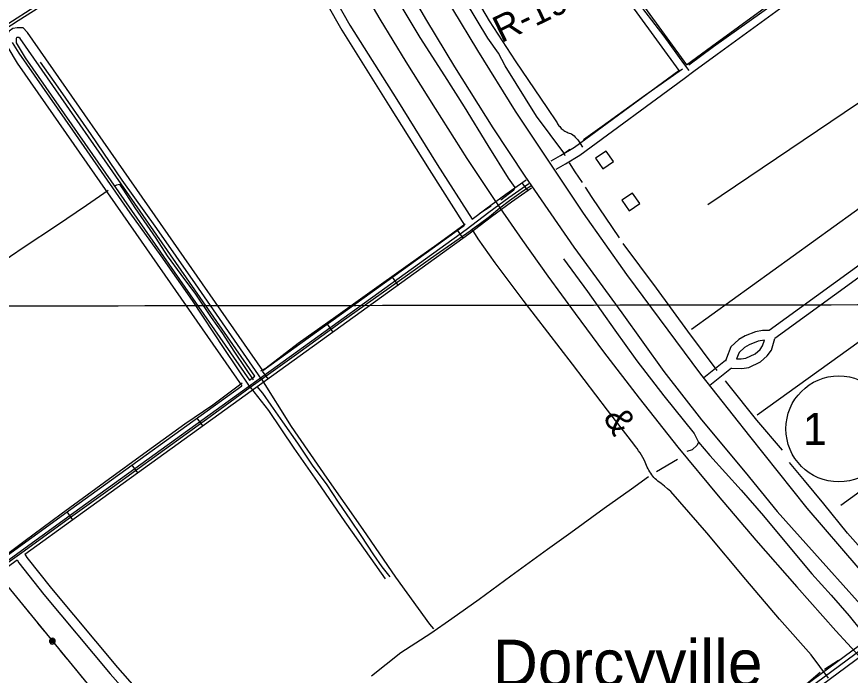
# Model space of a CAD drawing. Extents: x 3324125 to 3362000, y 600753 to 626151.
# Drawn here: x 3330131 to 3332729, y 611048 to 613099 of the extents above; entities that cross this region are included whole.
import ezdxf

# ---------------------------------------------------------------- set-up
doc = ezdxf.new("R2010")
doc.units = 0
for name, color, linetype in [('V-BLDG-OTLN', 7, 'Continuous'), ('V-DTCH-CNTR', 7, 'Continuous'), ('V-GRID-MAJR', 7, 'Continuous'), ('V-RAIL-IDEN', 7, 'Continuous'), ('V-RAIL-TRAK', 7, 'Continuous'), ('V-RIVR-RANG-IDEN', 7, 'Continuous'), ('V-ROAD-CNTR', 7, 'Continuous'), ('V-ROAD-IDEN', 7, 'Continuous'), ('V-TOPO-GNAM-IDEN', 7, 'Continuous'), ('V-TOPO-SHOR', 7, 'Continuous'), ('V-UTIL-LINE', 7, 'Continuous')]:
    doc.layers.add(name, color=color, linetype=linetype)

msp = doc.modelspace()

# ---------------------------------------------------------------- linework, layer by layer
at = {"layer": 'V-BLDG-OTLN'}
for points in [[(3331934.7, 612657.8), (3331957.1, 612624.7), (3331990.3, 612647.2), (3331967.8, 612680.3)], [(3332016.7, 612527.2), (3332039.1, 612494.1), (3332072.2, 612516.5), (3332049.8, 612549.6)]]:
    msp.add_lwpolyline(points, close=True, dxfattribs=at)
at = {"layer": 'V-DTCH-CNTR'}
msp.add_line((3331881, 612711.8), (3331893.9, 612692.5), dxfattribs=at)
for points in [[(3331510.5, 613243.8), (3331602.7, 613085.8), (3331684, 612961.1), (3331784.8, 612812.3), (3331813.1, 612771.5), (3331814.7, 612768.2), (3331816.4, 612765.1), (3331818.4, 612762), (3331820.5, 612759), (3331822.8, 612756.2), (3331825.2, 612753.5), (3331827.8, 612750.9), (3331830.5, 612748.5), (3331833.4, 612746.2), (3331836.3, 612744.1), (3331839.4, 612742.1), (3331842.6, 612740.3), (3331845.9, 612738.7), (3331849.2, 612737.3), (3331852.7, 612736.1), (3331856.1, 612735), (3331859.7, 612734.2), (3331863.7, 612730.9), (3331867.6, 612727.5), (3331871.2, 612723.8), (3331874.7, 612720), (3331878, 612716), (3331881, 612711.8)], [(3329755.3, 612855.6), (3330029.3, 613029.3), (3330259.4, 613178.2), (3330303.3, 613212.2), (3330298.1, 613227.7)], [(3332226.6, 612930.8), (3332209.3, 612953.2), (3332148.2, 613038.2), (3332054.3, 613161.7)], [(3330858.5, 611945), (3330777, 612065.4), (3330678.8, 612214.6), (3330581.2, 612354), (3330484.7, 612488.2), (3330404.4, 612603.5), (3330305.7, 612745.2), (3330209.8, 612882.3), (3330138.7, 612985.4), (3330117.3, 613018.2)], [(3330893.1, 611969.7), (3330809.9, 612091.3), (3330687.4, 612267), (3330567.3, 612439.2), (3330459.8, 612589.6), (3330362.8, 612731.9), (3330259.4, 612879.3), (3330204.5, 612956.5)], [(3329611.6, 611047.1), (3329753.3, 611148.2), (3329885.2, 611244.6), (3329999.3, 611324.9), (3330146.2, 611430), (3330290.8, 611535.2), (3330429, 611633.4), (3330572.5, 611737.9), (3330733.2, 611854), (3330858.5, 611945), (3330893.1, 611969.7), (3331002.8, 612048.1), (3331141.6, 612148), (3331291.4, 612254.3), (3331437.7, 612357.7), (3331544.3, 612432.3), (3331550.6, 612436.9), (3331571.9, 612452.5), (3331603.6, 612476.7), (3331636.6, 612503.3), (3331666, 612525.8), (3331710.4, 612557), (3331736.1, 612574)], [(3332660.5, 611038.6), (3332607, 611111.3), (3332508.2, 611222.7), (3332403, 611346.3), (3332281.5, 611491.7), (3332168.9, 611620.1), (3332159, 611628.5), (3332149, 611636.7), (3332138.8, 611644.6), (3332128.4, 611652.4), (3332124.4, 611656.1), (3332120.5, 611660), (3332116.7, 611664), (3332113.2, 611668.2), (3332109.8, 611672.5), (3332106.6, 611677), (3332103.5, 611681.6), (3332100.7, 611686.3), (3332098.1, 611691.1), (3332095.6, 611696), (3332093.4, 611701.1), (3332091.4, 611706.2), (3332089.5, 611711.4), (3332085.7, 611718.7), (3332081.7, 611726), (3332077.6, 611733.1), (3332073.2, 611740.2), (3332068.6, 611747.1), (3332063.9, 611753.9), (3332059, 611760.6), (3332053.9, 611767.1), (3331972.1, 611872.9), (3331862.7, 612016.7), (3331708.8, 612216.3), (3331622.2, 612331.8), (3331568.7, 612406.9), (3331550.6, 612436.9)], [(3330893.1, 611969.7), (3330986.1, 611822.3), (3331097, 611662.1), (3331209.1, 611501.4), (3331311.3, 611353.3), (3331417, 611207.6), (3331429.2, 611192.6)], [(3330858.5, 611945), (3330915.1, 611872.4), (3330994.3, 611754.9), (3331067, 611651.8), (3331153.1, 611525.6), (3331234, 611411.6), (3331279, 611348.2)]]:
    msp.add_lwpolyline(points, dxfattribs=at)
at = {"layer": 'V-GRID-MAJR'}
msp.add_spline([(3328225.8, 612195.7), (3333491.7, 612203), (3338757.5, 612211), (3344023.3, 612219.8), (3349289.1, 612229.4), (3354555, 612239.7), (3359820.8, 612250.8)], degree=3, dxfattribs=at)
at = {"layer": 'V-RAIL-TRAK'}
msp.add_lwpolyline([(3331144.3, 613293.1), (3331262.1, 613091.2), (3331343.2, 612958.3), (3331434.9, 612812.7), (3331533, 612657.3), (3331612.7, 612538.5), (3331636.6, 612503.3), (3331707.1, 612402.1), (3331786.1, 612290.3), (3331871.4, 612174.9), (3331958.9, 612054.7), (3332071, 611910.6), (3332191.5, 611758.7), (3332316.3, 611606.8), (3332434, 611468.3), (3332561.6, 611323.5), (3332683.5, 611186.4), (3332756.1, 611107.7)], dxfattribs=at)
at = {"layer": 'V-ROAD-CNTR'}
for p, q in [((3331705.2, 612581.6), (3331722.5, 612557.1)), ((3331503.7, 612433.5), (3331521.2, 612409.1)), ((3331300.9, 612287.3), (3331318.4, 612262.9)), ((3331098.1, 612141.1), (3331115.6, 612116.8)), ((3330895.3, 611994.9), (3330912.8, 611970.6)), ((3330692.5, 611848.8), (3330710, 611824.4)), ((3330489.6, 611702.6), (3330507.2, 611678.3)), ((3330286.8, 611556.4), (3330304.4, 611532.1))]:
    msp.add_line(p, q, dxfattribs=at)
for points in [[(3328654.4, 618531.3), (3329365.9, 617157.1), (3329945, 616043.4), (3330528.3, 614922), (3330989.5, 614026.8), (3331101.4, 613813.5), (3331202.1, 613623.7), (3331288.2, 613468), (3331370, 613325.9), (3331489, 613122.4), (3331566.5, 612992.9), (3331683.8, 612804.9), (3331896.1, 612486.7), (3332030.8, 612296.1), (3332261.4, 611985.3), (3332414.1, 611792.3), (3332593.4, 611567.9), (3332751.8, 611383.2), (3332947.9, 611162.2), (3333176.2, 610911.4), (3333408.7, 610672.1), (3333754.4, 610344.1), (3333997.3, 610124.4), (3334416.3, 609777.9)], [(3328581.7, 618486.8), (3329049, 617590.5), (3329407, 616899.8), (3329876.9, 615987.8), (3330239, 615290.1), (3330685.5, 614428.5), (3331002.8, 613822.2), (3331099.5, 613638), (3331200, 613453.8), (3331306.4, 613261.3), (3331407.9, 613087), (3331494.8, 612942.7), (3331614.1, 612752.9), (3331713.9, 612602.5), (3331866.6, 612380.6), (3332016.4, 612177), (3332147.9, 611993.9), (3332265.1, 611843.6), (3332400.7, 611680.6), (3332500.3, 611558.3), (3332661.3, 611378.2), (3332840.8, 611178.7), (3333031, 610974.2)], [(3332218.1, 612948.7), (3332296.1, 613005.9), (3333210.5, 613671.6)], [(3332241.4, 612928.5), (3332313.8, 612981.7), (3333228.1, 613647.4)], [(3330922.2, 613501.4), (3330944, 613469.2), (3331169.3, 613072.5), (3331314.8, 612840.5)], [(3330893.9, 613489.7), (3330918.5, 613453.4), (3331143.6, 613057.1), (3331289.8, 612823.8)], [(3331870.9, 613375.1), (3332194, 612930.9)], [(3331895.2, 613392.7), (3332218.1, 612948.7)], [(3330163.6, 613050.3), (3330150.8, 613063.8), (3330131.7, 613064.3), (3330118.9, 613061.4), (3330107, 613053.8), (3330098.6, 613037.6), (3330099.3, 613009), (3330103.3, 613002.3)], [(3333838.9, 613066.9), (3333796.8, 613035.5), (3333796.8, 613035.5), (3333783.8, 613040.6), (3333767.8, 613042.2), (3333756.2, 613042.5), (3333735, 613034.3), (3333720.7, 613023.9), (3332476, 612121), (3332455.1, 612121), (3332433.6, 612117.1), (3332400.7, 612104.4), (3332381.3, 612093), (3332356.4, 612070.9), (3332342.7, 612034.9), (3332339.7, 612026.5), (3332340.1, 612028), (3332272.4, 611973.8)], [(3330541.3, 612455.7), (3330141.3, 613030.2), (3330137.6, 613034.1), (3330134.6, 613034.2), (3330130.7, 613033.3), (3330130, 613032.9), (3330128.8, 613030.6), (3330129.1, 613017.6)], [(3330562.1, 612478.3), (3330164.6, 613049.3), (3330163.6, 613050.3)], [(3330129.1, 613017.6), (3330157.5, 612970.1), (3330529, 612436.9)], [(3330103.3, 613002.3), (3330132.3, 612953.8), (3330502.1, 612423.1)], [(3331796.7, 612649.8), (3331825.3, 612666.5), (3331869.4, 612692.7), (3332194, 612930.9)], [(3332210.7, 612906), (3332241.4, 612928.5)], [(3331811.8, 612623.9), (3331840.5, 612640.7), (3331885.9, 612667.6), (3332210.7, 612906)], [(3331289.8, 612823.8), (3331416.1, 612622.3), (3331525.8, 612449.5)], [(3331314.8, 612840.5), (3331441.5, 612638.3), (3331549.7, 612467.8)], [(3333446, 612787.6), (3332493.8, 612096.8)], [(3331549.7, 612467.8), (3331592.6, 612500.7), (3331655.1, 612546.3), (3331718, 612590.6)], [(3331726.6, 612578.3), (3331663.9, 612534.1), (3331601.6, 612488.7), (3331531, 612434.7), (3330308.3, 611553.4), (3329430.7, 610917.9), (3328599.2, 610316), (3328226.3, 610054.2)], [(3330156.2, 611424.8), (3330317.1, 611541.3), (3331540, 612422.6), (3331610.5, 612476.7), (3331672.6, 612521.9), (3331735.2, 612566)], [(3330897.5, 611996.5), (3330562.1, 612478.3)], [(3330529, 612436.9), (3330856.4, 611966.9)], [(3330873.1, 611979), (3330541.3, 612455.7)], [(3330897.5, 611996.5), (3331522.1, 612446.7), (3331525.8, 612449.5)], [(3330502.1, 612423.1), (3330832.1, 611949.4)], [(3332358.3, 612004.2), (3332390.1, 612002.8), (3332412.2, 612006.1), (3332448.4, 612023.9), (3332469.9, 612042.2), (3332482.6, 612060.4), (3332493.8, 612096.8)], [(3332374.2, 612033.5), (3332388.5, 612032.9), (3332403.1, 612035.1), (3332431.8, 612049.2), (3332447.6, 612062.6), (3332455.3, 612073.7), (3332460.8, 612091.5)], [(3332460.8, 612091.5), (3332441.8, 612088.1), (3332413.8, 612077.3), (3332399, 612068.6), (3332381.8, 612053.3), (3332374.2, 612033.5)], [(3332358.3, 612004.2), (3332291.1, 611950.4)], [(3330856.4, 611966.9), (3330873.1, 611979)], [(3329934, 611300.9), (3330299.6, 611565.6), (3330832.1, 611949.4)], [(3330156.2, 611424.8), (3330161.8, 611415), (3330238.6, 611318), (3330444.9, 611072.5), (3330684.1, 610801.4), (3330758.3, 610722.6)], [(3328796.4, 610440.2), (3329439.5, 610905.7), (3330131.8, 611407.1)], [(3330131.8, 611407.1), (3330136.8, 611398.2), (3330215.3, 611299), (3330422.1, 611052.9), (3330661.9, 610781.2), (3330736.5, 610702.1)], [(3331645.4, 610320.3), (3331917.2, 610521.1), (3332828.9, 611195.1)], [(3332837.9, 611183), (3331926.1, 610509.1), (3330849.7, 609713.3), (3329925.5, 609026.5), (3329083.5, 608406), (3328229.3, 607781.1)], [(3331661.5, 610294.8), (3331935, 610497), (3332846.8, 611171)]]:
    msp.add_lwpolyline(points, dxfattribs=at)
at = {"layer": 'V-ROAD-IDEN'}
msp.add_circle((3332693, 611815.1), 165, dxfattribs=at)
at = {"layer": 'V-TOPO-SHOR'}
for p, q in [((3332437.9, 611859.3), (3333900.4, 612907.6)), ((3331840.4, 612665.5), (3331836.3, 612674.3)), ((3331680.3, 612558.2), (3331639.3, 612526.9)), ((3331609.4, 612508.2), (3331573.9, 612485.5)), ((3332698.7, 611578.1), (3333291.9, 612007.6)), ((3332190.3, 611719.9), (3332124.9, 611681.8)), ((3332692.2, 611094.4), (3332647.8, 611065.6))]:
    msp.add_line(p, q, dxfattribs=at)
for points in [[(3331854.7, 612684.6), (3331838.4, 612673.6), (3331836.3, 612674.3), (3331751, 612789.3), (3331652.7, 612945.9), (3331632.2, 612984.7), (3331598.8, 613031.7), (3331529.8, 613146.7), (3331476.5, 613244.1), (3331461.5, 613272), (3331434.9, 613313.5), (3331395.3, 613382.2), (3331364.6, 613438.8), (3331350.9, 613463.9), (3331317.5, 613516.4), (3331249.8, 613645.7), (3331183.6, 613768.2), (3331105.7, 613911.2), (3331033.3, 614056.9), (3330977.3, 614172.6), (3330936.3, 614253.7)], [(3331680.3, 612558.2), (3331683.7, 612566.3), (3331663, 612596.2), (3331600.1, 612697.9), (3331526.4, 612817.4), (3331465.3, 612914.5), (3331388.1, 613033.4), (3331316, 613154.1), (3331235.9, 613295.5), (3331180, 613395.5), (3331114.8, 613520.2), (3331067.6, 613606.4), (3331042.2, 613650.1), (3331029.1, 613662.2)], [(3330942.6, 613609.9), (3330885.3, 613566.2), (3330849.7, 613544.7), (3330781.8, 613500.1), (3330708.7, 613449.9), (3330657.4, 613418.3), (3330604.9, 613390.7), (3330547.1, 613351.8), (3330472.8, 613306.1), (3330409, 613260.7), (3330325.4, 613206.4), (3330264.4, 613167.9), (3330203, 613128.6), (3330135.5, 613086.1), (3330071.3, 613045.2)], [(3332797.4, 613358.2), (3332674.2, 613269.5), (3332524.4, 613163.7), (3332302.5, 613004.7), (3332225, 612948)], [(3332284.5, 612513.8), (3333051.5, 613030.3), (3333143.6, 612907.6), (3333189.6, 612958.7)], [(3332205.9, 612935), (3332090.2, 612853.8), (3331955.4, 612756.9), (3331896.9, 612715.3)], [(3332233.4, 612125.2), (3333184.5, 612810.4), (3333148.7, 612851.3)], [(3331894.3, 612582.4), (3331871.1, 612615.1), (3331853.4, 612643.7)], [(3330868.4, 611967.8), (3330845, 612002.8), (3330808.3, 612057.4), (3330772.7, 612112), (3330738, 612161.6), (3330688.7, 612234.1), (3330643.2, 612295.4), (3330600.9, 612354.1), (3330565, 612408.7), (3330500.2, 612503.8), (3330464.7, 612558), (3330455.1, 612572.1), (3330451.7, 612575.9), (3330441.7, 612573.8), (3330434.7, 612570.8)], [(3332009, 612409.5), (3331924.4, 612535.5), (3331903.2, 612568.1)], [(3330415.5, 612557.4), (3330348.4, 612510.2), (3330254.6, 612447.5), (3330153.7, 612380.7), (3330067.4, 612322.6), (3329985.7, 612269.5), (3329905.7, 612215.1), (3329830.7, 612167.1), (3329745.2, 612111.1), (3329648.9, 612045.4), (3329578.1, 611999.4), (3329496.4, 611945.1), (3329437.6, 611907.1), (3329361.8, 611856.9), (3329278, 611799.6), (3329200, 611747.8), (3329130, 611703.9), (3329054.6, 611652.1), (3328997.1, 611611.5), (3328970.9, 611597.2)], [(3331528.6, 612452.3), (3331439.5, 612388.1), (3331350.7, 612324.5), (3331231.1, 612239.5), (3331125.3, 612163.7), (3331007.3, 612080.7), (3330908, 612004.1), (3330890.4, 611994.6)], [(3332313.4, 611997.1), (3332222, 612119.6), (3332124.4, 612253), (3332020.6, 612392.5)], [(3331835.2, 612345.1), (3331909.6, 612243.4), (3331994.3, 612122.7), (3332063.4, 612027.4), (3332147.5, 611918.2), (3332242, 611800.4), (3332255.2, 611773.4), (3332251.2, 611764.8), (3332235.7, 611750.4), (3332218.6, 611744.2)], [(3332516.8, 611748.7), (3332436.9, 611841.9), (3332346.8, 611954.9), (3332340, 611964.4)], [(3330833.1, 611957.4), (3330741.9, 611889.1), (3330654.3, 611830.3), (3330538, 611746.1), (3330404.3, 611647.7), (3330269, 611549.3), (3330156.7, 611466.6), (3330042.4, 611381.2), (3329925.9, 611302.8)], [(3331294.8, 611354.2), (3331269.3, 611385.5), (3331243.8, 611422.6), (3331204.5, 611483), (3331172.3, 611531), (3331133.4, 611587.2), (3331097.9, 611641.4), (3331052.8, 611702.3), (3331006.8, 611771), (3330960.4, 611837.3), (3330923.2, 611889), (3330897.3, 611926.5), (3330879.7, 611946.9)], [(3332255.2, 611773.4), (3332290.9, 611732.1), (3332388.8, 611624.7), (3332458, 611544.8), (3332529.4, 611458.1), (3332608.3, 611363.8), (3332669.3, 611297.2), (3332725.2, 611233.5), (3332763.8, 611185.2), (3332777.4, 611163.7)], [(3332795.2, 611405.7), (3332720.1, 611490.8), (3332646.4, 611582), (3332585.7, 611654.1), (3332539.3, 611710.6)], [(3332099.8, 611665.6), (3332046.7, 611627.6), (3331961.9, 611566.8), (3331857.6, 611491.9), (3331784.9, 611439.6), (3331670.2, 611356.6), (3331572.1, 611283.7), (3331486.8, 611223.7), (3331421.4, 611178.4), (3331327.7, 611117.6), (3331236.8, 611044.7)], [(3332634.6, 611056.9), (3332584.5, 611014.5), (3332499.8, 610953.3), (3332408.2, 610885.1), (3332332.2, 610830.3), (3332246.9, 610766.7), (3332147.8, 610693.9), (3332044.1, 610617.1), (3331971, 610561.7), (3331882.3, 610496.4), (3331765.3, 610409.8), (3331687.6, 610353.2), (3331639.2, 610319.9)]]:
    msp.add_lwpolyline(points, dxfattribs=at)
at = {"layer": 'V-UTIL-LINE'}
for points in [[(3328236.3, 613587.3), (3328405.4, 613379.6), (3328937.8, 612727.6), (3329480.1, 612077.2), (3330016.7, 611428.3), (3330555.9, 610771.6), (3331085.8, 610130.8), (3331625.2, 609459.8), (3332162.6, 608808.1), (3332702, 608152.5)], [(3330148.4, 611267.9), (3330170, 611241.6)], [(3330195.4, 611210.7), (3330216.9, 611184.4)], [(3330241.7, 611154.3), (3330242.5, 611157), (3330240.3, 611156.3), (3330239.6, 611153.6), (3330241.7, 611151.6), (3330244.4, 611153.6), (3330245, 611158.3), (3330241.1, 611160.1), (3330236.7, 611158.2), (3330236, 611153.6), (3330238, 611149.6), (3330242.8, 611148.7), (3330247.2, 611152), (3330248.6, 611160), (3330245.9, 611162.2), (3330242.6, 611163.2), (3330239.1, 611162.9), (3330236, 611161.2), (3330233.7, 611158.5), (3330232.7, 611155.2), (3330233.1, 611151.7), (3330234.7, 611148.6), (3330237.4, 611146.3), (3330240.8, 611145.3), (3330244.3, 611145.7), (3330247.4, 611147.3), (3330249.6, 611150), (3330250.6, 611153.4), (3330250.3, 611156.9), (3330248.6, 611160)], [(3330266.4, 611124.1), (3330288, 611097.9)], [(3330313.4, 611066.9), (3330335, 611040.7)]]:
    msp.add_lwpolyline(points, dxfattribs=at)

# ---------------------------------------------------------------- texts
at = {"layer": 'V-RAIL-IDEN'}
msp.add_text('&', height=83, rotation=300, dxfattribs=at).set_placement((3331956.6, 611852.1))
at = {"layer": 'V-RIVR-RANG-IDEN'}
msp.add_text('R-194.25', height=83, rotation=25.7857, dxfattribs=at).set_placement((3331641.1, 613015.9))
at = {"layer": 'V-ROAD-IDEN'}
msp.add_text(' 1 ', height=100, rotation=359.9873, dxfattribs=at).set_placement((3332544.1, 611765.1))
at = {"layer": 'V-TOPO-GNAM-IDEN'}
msp.add_text('Dorcyville', height=145, rotation=359.9873, dxfattribs=at).set_placement((3331614.7, 611013.9))

doc.saveas('drawing.dxf')
